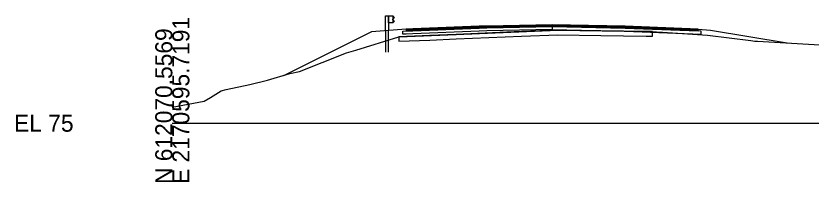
# Model space of a CAD drawing. Extents: x -26 to 1303, y -3010 to 12023.
# Drawn here: x -25.7 to 104.9, y 11990.3 to 12017.7 of the extents above; entities that cross this region are included whole.
import ezdxf

# ---------------------------------------------------------------- set-up
doc = ezdxf.new("R2010")
doc.units = 0
for name, color, linetype in [('RD_GPK_XS_Cell', 7, 'Continuous'), ('RD_PD_Final_TrvlWay', 7, 'Continuous'), ('RD_XS_Base', 7, 'Continuous'), ('RD_XS_ExGround', 7, 'Continuous'), ('RD_XS_ExPaveRet', 7, 'Continuous'), ('RD_XS_GR', 7, 'Continuous'), ('RD_XS_Greenside', 7, 'Continuous'), ('RD_XS_Pave', 7, 'Continuous'), ('RD_XS_PaveOvlay_CP', 7, 'Continuous'), ('RD_XS_TieSlope', 7, 'Continuous')]:
    doc.layers.add(name, color=color, linetype=linetype)

msp = doc.modelspace()

# ---------------------------------------------------------------- linework, layer by layer
at = {"layer": 'RD_GPK_XS_Cell'}
msp.add_line((0, 12000), (150, 12000), dxfattribs=at)
at = {"layer": 'RD_PD_Final_TrvlWay'}
msp.add_lwpolyline([(35.54, 12011.66), (35.54, 12015.26), (35.04, 12015.22), (35.04, 12011.66)], dxfattribs=at)
at = {"layer": 'RD_XS_Base'}
for p, q in [((37.89, 12014.7), (37.89, 12015.15)), ((37.89, 12015.15), (37.94, 12015.15)), ((37.94, 12015.15), (38.39, 12015.17)), ((38.39, 12015.17), (39.51, 12015.22)), ((39.51, 12015.22), (50.39, 12015.65)), ((50.39, 12015.15), (39.51, 12014.72)), ((50.39, 12015.65), (51.68, 12015.68)), ((51.68, 12015.18), (50.39, 12015.15)), ((51.68, 12015.68), (62.39, 12015.89)), ((62.39, 12015.39), (51.68, 12015.18)), ((62.39, 12015.91), (62.39, 12016.05)), ((62.39, 12016.05), (62.39, 12015.47)), ((62.39, 12015.89), (62.39, 12016.05)), ((62.39, 12016.05), (62.39, 12015.39)), ((62.39, 12015.89), (62.39, 12015.91)), ((62.39, 12015.89), (62.39, 12015.45)), ((62.39, 12015.89), (62.39, 12015.39)), ((74.39, 12015.65), (62.39, 12015.89)), ((62.39, 12015.89), (62.39, 12015.89)), ((62.39, 12015.47), (62.39, 12015.39)), ((62.39, 12015.45), (62.39, 12015.39)), ((62.39, 12015.39), (62.39, 12015.39)), ((62.39, 12015.39), (62.39, 12015.39)), ((62.39, 12015.39), (74.39, 12015.15)), ((86.39, 12015.17), (74.39, 12015.65)), ((74.39, 12015.15), (86.89, 12014.65)), ((76.39, 12015.57), (76.39, 12015.57)), ((76.39, 12015.07), (76.39, 12015.07)), ((86.89, 12015.15), (86.39, 12015.17)), ((86.39, 12015.17), (86.39, 12015.17)), ((86.89, 12014.65), (86.89, 12015.15)), ((86.89, 12015.15), (86.89, 12015.15)), ((37.89, 12014.65), (37.89, 12014.7)), ((37.94, 12014.65), (37.89, 12014.65)), ((38.39, 12014.67), (37.94, 12014.65)), ((39.51, 12014.72), (38.39, 12014.67)), ((86.89, 12014.65), (86.89, 12014.65)), ((86.89, 12014.65), (86.89, 12014.65))]:
    msp.add_line(p, q, dxfattribs=at)
at = {"layer": 'RD_XS_ExGround'}
msp.add_lwpolyline([(0, 12002.63), (5.24, 12003.64), (6.25, 12004.22), (8.04, 12005.31), (8.83, 12005.56), (12.76, 12006.37), (15.65, 12007.1), (19.31, 12008.2), (20.9, 12008.51), (24.64, 12009.97), (28.59, 12011.6), (30.14, 12012.03), (37.21, 12014.22), (46.61, 12014.61), (63.31, 12015.31), (77.83, 12015.09), (78.86, 12015.07), (80.2, 12014.99), (80.55, 12014.97), (87.94, 12014.49), (95.02, 12013.58), (95.67, 12013.5), (96.15, 12013.51), (111.02, 12012.63)], dxfattribs=at)
at = {"layer": 'RD_XS_ExPaveRet'}
for points in [[(78.86, 12015.07), (78.86, 12015.07), (77.83, 12015.09), (70.41, 12015.2), (63.31, 12015.31), (57.38, 12015.06), (46.61, 12014.61), (42.28, 12014.43), (37.21, 12014.22), (37.21, 12013.97), (37.21, 12013.47), (42.28, 12013.68), (46.61, 12013.86), (57.38, 12014.31), (63.31, 12014.56), (70.41, 12014.45), (77.83, 12014.34), (78.86, 12014.32), (78.86, 12014.32), (78.86, 12014.32), (78.86, 12014.32), (78.86, 12014.69), (78.86, 12015.07), (78.86, 12015.07), (78.86, 12015.07)], [(78.86, 12015.07), (78.86, 12015.07), (77.83, 12015.09), (70.41, 12015.2), (63.31, 12015.31), (57.38, 12015.06), (46.61, 12014.61), (42.28, 12014.43), (37.21, 12014.22), (37.21, 12013.97), (37.21, 12013.47), (42.28, 12013.68), (46.61, 12013.86), (57.38, 12014.31), (63.31, 12014.56), (70.41, 12014.45), (77.83, 12014.34), (78.86, 12014.32), (78.86, 12014.32), (78.86, 12014.32), (78.86, 12014.69), (78.86, 12015.07), (78.86, 12015.07)]]:
    msp.add_lwpolyline(points, dxfattribs=at)
at = {"layer": 'RD_XS_GR'}
for p, q in [((35.04, 12015.22), (35.04, 12017.66)), ((35.04, 12017.66), (35.29, 12017.66)), ((35.29, 12017.66), (35.54, 12017.66)), ((35.54, 12017.66), (35.54, 12015.26)), ((35.54, 12016.49), (35.54, 12017.66)), ((35.54, 12017.66), (36.21, 12017.66)), ((36.21, 12016.49), (35.54, 12016.49)), ((36.21, 12017.66), (36.21, 12016.49)), ((36.46, 12017.39), (36.21, 12017.66)), ((36.21, 12017.66), (36.21, 12016.59)), ((36.21, 12017.07), (36.24, 12017.1)), ((36.46, 12016.81), (36.21, 12017.07)), ((36.21, 12016.59), (36.21, 12016.49)), ((36.21, 12016.49), (36.24, 12016.52)), ((36.24, 12017.1), (36.48, 12017.37)), ((36.24, 12016.52), (36.48, 12016.78)), ((36.48, 12017.37), (36.46, 12017.39)), ((36.48, 12016.78), (36.46, 12016.81)), ((35.54, 12015.26), (35.04, 12015.22))]:
    msp.add_line(p, q, dxfattribs=at)
at = {"layer": 'RD_XS_Greenside'}
for p, q in [((88.39, 12015.33), (101.01, 12013.22)), ((32.73, 12015.04), (18.26, 12007.8))]:
    msp.add_line(p, q, dxfattribs=at)
at = {"layer": 'RD_XS_Pave'}
for p, q in [((39.51, 12015.53), (38.39, 12015.49)), ((38.39, 12015.49), (38.39, 12015.35)), ((39.51, 12015.38), (38.39, 12015.33)), ((38.39, 12015.33), (39.51, 12015.38)), ((38.39, 12015.35), (38.39, 12015.33)), ((38.39, 12015.33), (38.39, 12015.19)), ((38.39, 12015.17), (39.51, 12015.22)), ((38.39, 12015.19), (38.39, 12015.17)), ((50.39, 12015.97), (39.51, 12015.53)), ((50.39, 12015.81), (39.51, 12015.38)), ((39.51, 12015.38), (50.39, 12015.81)), ((39.51, 12015.22), (50.39, 12015.65)), ((51.68, 12015.99), (50.39, 12015.97)), ((51.68, 12015.84), (50.39, 12015.81)), ((50.39, 12015.81), (51.68, 12015.84)), ((50.39, 12015.65), (51.68, 12015.68)), ((62.39, 12016.21), (51.68, 12015.99)), ((62.39, 12016.05), (51.68, 12015.84)), ((51.68, 12015.84), (62.39, 12016.05)), ((51.68, 12015.68), (62.39, 12015.89)), ((74.39, 12015.97), (62.39, 12016.21)), ((62.39, 12015.91), (62.39, 12016.05)), ((62.39, 12016.05), (62.39, 12015.91)), ((62.39, 12015.89), (62.39, 12016.05)), ((62.39, 12016.05), (74.39, 12015.81)), ((74.39, 12015.81), (62.39, 12016.05)), ((62.39, 12016.05), (62.39, 12015.89)), ((62.39, 12015.89), (62.39, 12015.91)), ((62.39, 12015.91), (62.39, 12015.89)), ((62.39, 12015.89), (62.39, 12015.89)), ((62.39, 12015.89), (62.39, 12015.89)), ((62.39, 12015.89), (74.39, 12015.65)), ((86.39, 12015.49), (74.39, 12015.97)), ((74.39, 12015.81), (86.39, 12015.33)), ((86.39, 12015.33), (74.39, 12015.81)), ((74.39, 12015.65), (86.39, 12015.17)), ((76.39, 12015.89), (76.39, 12015.89)), ((76.39, 12015.73), (76.39, 12015.73)), ((76.39, 12015.73), (76.39, 12015.73)), ((76.39, 12015.57), (76.39, 12015.57)), ((86.39, 12015.33), (86.39, 12015.49)), ((86.39, 12015.49), (86.39, 12015.49)), ((86.39, 12015.33), (86.39, 12015.33)), ((86.39, 12015.33), (86.39, 12015.33)), ((86.39, 12015.17), (86.39, 12015.33)), ((86.39, 12015.33), (86.39, 12015.33)), ((86.39, 12015.17), (86.39, 12015.17)), ((86.39, 12015.17), (86.39, 12015.17))]:
    msp.add_line(p, q, dxfattribs=at)
at = {"layer": 'RD_XS_PaveOvlay_CP'}
for p, q in [((38.39, 12015.49), (50.39, 12015.97)), ((50.39, 12015.97), (62.39, 12016.21)), ((62.39, 12016.21), (74.39, 12015.97)), ((74.39, 12015.97), (86.39, 12015.49))]:
    msp.add_line(p, q, dxfattribs=at)
at = {"layer": 'RD_XS_TieSlope'}
for p, q in [((38.39, 12015.49), (32.73, 12015.04)), ((86.39, 12015.49), (88.39, 12015.33))]:
    msp.add_line(p, q, dxfattribs=at)

# ---------------------------------------------------------------- texts
at = {"layer": 'RD_GPK_XS_Cell'}
for s, p in [('E 2170595.7191', (2.8, 11990)), ('N 612070.5569', (0, 11990))]:
    msp.add_text(s, height=2.8, rotation=90, dxfattribs=at).set_placement(p)
msp.add_text('EL 75', height=2.8, dxfattribs=at).set_placement((-26, 11998.6))

doc.saveas('drawing.dxf')
